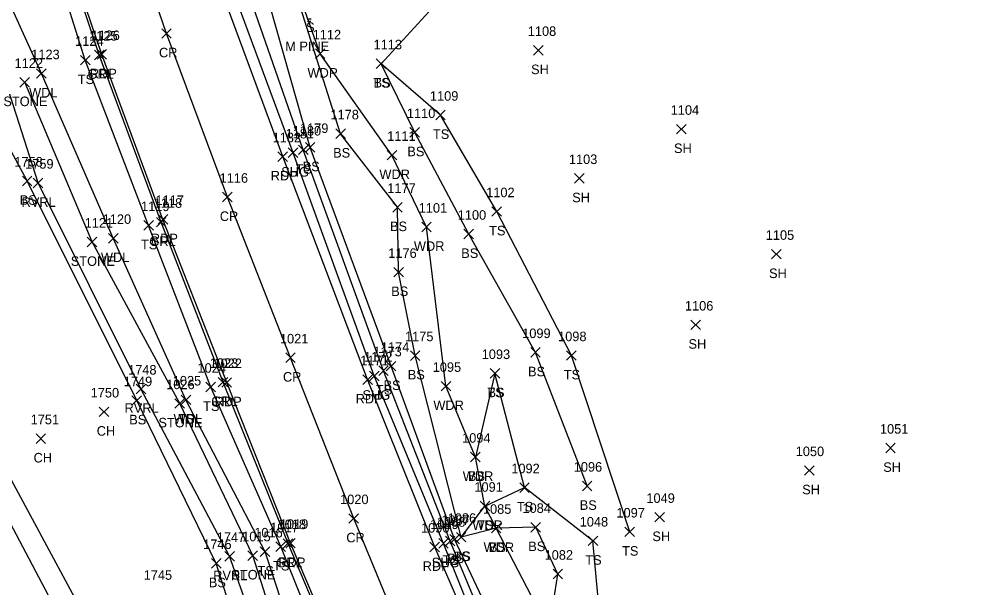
# Model space of a CAD drawing. Extents: x 1545627 to 1546562, y 571176 to 576667.
# Drawn here: x 1546172.5 to 1546373.5, y 571704.9 to 571824 of the extents above; entities that cross this region are included whole.
import ezdxf

# ---------------------------------------------------------------- set-up
doc = ezdxf.new("R2010")
doc.units = 0
for name, color, linetype in [('L_A', 7, 'Continuous'), ('L_C', 7, 'Continuous'), ('L_I', 7, 'Continuous'), ('L_TIC', 7, 'Continuous'), ('LASF', 7, 'Continuous'), ('LAWA', 7, 'Continuous'), ('LAWE', 7, 'Continuous'), ('LELB', 7, 'Continuous'), ('LTC', 7, 'Continuous'), ('P_A', 7, 'Continuous'), ('P_I', 7, 'Continuous'), ('P_TIC', 7, 'Continuous'), ('PET', 7, 'Continuous'), ('PRC', 7, 'Continuous'), ('PSU', 7, 'Continuous'), ('R_A', 7, 'Continuous'), ('R_I', 7, 'Continuous'), ('R_TIC', 7, 'Continuous'), ('RGR', 7, 'Continuous')]:
    doc.layers.add(name, color=color, linetype=linetype)

msp = doc.modelspace()

# ---------------------------------------------------------------- linework, layer by layer
at = {"layer": 'L_TIC'}
for points in [[(1546234.49, 571815.76), (1546236.49, 571817.76)], [(1546236.49, 571815.76), (1546234.49, 571817.76)], [(1546280.13, 571816.49), (1546282.13, 571818.49)], [(1546282.13, 571816.49), (1546280.13, 571818.49)], [(1546185.37, 571814.41), (1546187.37, 571816.41)], [(1546187.37, 571814.41), (1546185.37, 571816.41)], [(1546247.23, 571813.68), (1546249.23, 571815.68)], [(1546249.23, 571813.68), (1546247.23, 571815.68)], [(1546247.23, 571813.68), (1546249.23, 571815.68)], [(1546249.23, 571813.68), (1546247.23, 571815.68)], [(1546172.69, 571809.79), (1546174.69, 571811.79)], [(1546174.69, 571809.79), (1546172.69, 571811.79)], [(1546176.19, 571811.62), (1546178.19, 571813.62)], [(1546178.19, 571811.62), (1546176.19, 571813.62)], [(1546259.68, 571802.92), (1546261.68, 571804.92)], [(1546261.68, 571802.92), (1546259.68, 571804.92)], [(1546310.03, 571799.97), (1546312.03, 571801.97)], [(1546312.03, 571799.97), (1546310.03, 571801.97)], [(1546238.77, 571799.02), (1546240.77, 571801.02)], [(1546240.77, 571799.02), (1546238.77, 571801.02)], [(1546254.29, 571799.29), (1546256.29, 571801.29)], [(1546256.29, 571799.29), (1546254.29, 571801.29)], [(1546232.4, 571796.16), (1546234.4, 571798.16)], [(1546234.4, 571796.16), (1546232.4, 571798.16)], [(1546230.96, 571795.63), (1546232.96, 571797.63)], [(1546232.96, 571795.63), (1546230.96, 571797.63)], [(1546249.52, 571794.52), (1546251.52, 571796.52)], [(1546251.52, 571794.52), (1546249.52, 571796.52)], [(1546288.73, 571789.66), (1546290.73, 571791.66)], [(1546290.73, 571789.66), (1546288.73, 571791.66)], [(1546173.21, 571789.13), (1546175.21, 571791.13)], [(1546175.21, 571789.13), (1546173.21, 571791.13)], [(1546175.48, 571788.7), (1546177.48, 571790.7)], [(1546177.48, 571788.7), (1546175.48, 571790.7)], [(1546250.67, 571783.62), (1546252.67, 571785.62)], [(1546252.67, 571783.62), (1546250.67, 571785.62)], [(1546271.43, 571782.72), (1546273.43, 571784.72)], [(1546273.43, 571782.72), (1546271.43, 571784.72)], [(1546198.61, 571779.81), (1546200.61, 571781.81)], [(1546200.61, 571779.81), (1546198.61, 571781.81)], [(1546256.75, 571779.48), (1546258.75, 571781.48)], [(1546258.75, 571779.48), (1546256.75, 571781.48)], [(1546265.57, 571778), (1546267.57, 571780)], [(1546267.57, 571778), (1546265.57, 571780)], [(1546186.79, 571776.34), (1546188.79, 571778.34)], [(1546188.79, 571776.34), (1546186.79, 571778.34)], [(1546191.22, 571777.13), (1546193.22, 571779.13)], [(1546193.22, 571777.13), (1546191.22, 571779.13)], [(1546329.91, 571773.79), (1546331.91, 571775.79)], [(1546331.91, 571773.79), (1546329.91, 571775.79)], [(1546250.92, 571770.02), (1546252.92, 571772.02)], [(1546252.92, 571770.02), (1546250.92, 571772.02)], [(1546313.06, 571758.99), (1546315.06, 571760.99)], [(1546315.06, 571758.99), (1546313.06, 571760.99)], [(1546254.38, 571752.56), (1546256.38, 571754.56)], [(1546256.38, 571752.56), (1546254.38, 571754.56)], [(1546279.54, 571753.22), (1546281.54, 571755.22)], [(1546281.54, 571753.22), (1546279.54, 571755.22)], [(1546287.05, 571752.57), (1546289.05, 571754.57)], [(1546289.05, 571752.57), (1546287.05, 571754.57)], [(1546249.32, 571750.35), (1546251.32, 571752.35)], [(1546251.32, 571750.35), (1546249.32, 571752.35)], [(1546247.75, 571749.39), (1546249.75, 571751.39)], [(1546249.75, 571749.39), (1546247.75, 571751.39)], [(1546271.06, 571748.83), (1546273.06, 571750.83)], [(1546273.06, 571748.83), (1546271.06, 571750.83)], [(1546271.06, 571748.83), (1546273.06, 571750.83)], [(1546273.06, 571748.83), (1546271.06, 571750.83)], [(1546197.01, 571745.58), (1546199.01, 571747.58)], [(1546199.01, 571745.58), (1546197.01, 571747.58)], [(1546211.6, 571745.96), (1546213.6, 571747.96)], [(1546213.6, 571745.96), (1546211.6, 571747.96)], [(1546260.81, 571746.15), (1546262.81, 571748.15)], [(1546262.81, 571746.15), (1546260.81, 571748.15)], [(1546196.12, 571743.15), (1546198.12, 571745.15)], [(1546198.12, 571743.15), (1546196.12, 571745.15)], [(1546205.12, 571742.52), (1546207.12, 571744.52)], [(1546207.12, 571742.52), (1546205.12, 571744.52)], [(1546206.43, 571743.29), (1546208.43, 571745.29)], [(1546208.43, 571743.29), (1546206.43, 571745.29)], [(1546206.43, 571743.29), (1546208.43, 571745.29)], [(1546208.43, 571743.29), (1546206.43, 571745.29)], [(1546189.27, 571740.78), (1546191.27, 571742.78)], [(1546191.27, 571740.78), (1546189.27, 571742.78)], [(1546176.06, 571735.17), (1546178.06, 571737.17)], [(1546178.06, 571735.17), (1546176.06, 571737.17)], [(1546353.8, 571733.2), (1546355.8, 571735.2)], [(1546355.8, 571733.2), (1546353.8, 571735.2)], [(1546266.97, 571731.31), (1546268.97, 571733.31)], [(1546268.97, 571731.31), (1546266.97, 571733.31)], [(1546266.97, 571731.31), (1546268.97, 571733.31)], [(1546268.97, 571731.31), (1546266.97, 571733.31)], [(1546336.84, 571728.5), (1546338.84, 571730.5)], [(1546338.84, 571728.5), (1546336.84, 571730.5)], [(1546277.25, 571724.92), (1546279.25, 571726.92)], [(1546279.25, 571724.92), (1546277.25, 571726.92)], [(1546277.25, 571724.92), (1546279.25, 571726.92)], [(1546279.25, 571724.92), (1546277.25, 571726.92)], [(1546290.36, 571725.25), (1546292.36, 571727.25)], [(1546292.36, 571725.25), (1546290.36, 571727.25)], [(1546268.96, 571721.04), (1546270.96, 571723.04)], [(1546270.96, 571721.04), (1546268.96, 571723.04)], [(1546268.96, 571721.04), (1546270.96, 571723.04)], [(1546270.96, 571721.04), (1546268.96, 571723.04)], [(1546305.52, 571718.71), (1546307.52, 571720.71)], [(1546307.52, 571718.71), (1546305.52, 571720.71)], [(1546271.32, 571716.42), (1546273.32, 571718.42)], [(1546273.32, 571716.42), (1546271.32, 571718.42)], [(1546271.32, 571716.42), (1546273.32, 571718.42)], [(1546273.32, 571716.42), (1546271.32, 571718.42)], [(1546279.59, 571716.61), (1546281.59, 571718.61)], [(1546281.59, 571716.61), (1546279.59, 571718.61)], [(1546299.25, 571715.65), (1546301.25, 571717.65)], [(1546301.25, 571715.65), (1546299.25, 571717.65)], [(1546261.69, 571713.72), (1546263.69, 571715.72)], [(1546263.69, 571713.72), (1546261.69, 571715.72)], [(1546262.63, 571714.11), (1546264.63, 571716.11)], [(1546264.63, 571714.11), (1546262.63, 571716.11)], [(1546264, 571714.53), (1546266, 571716.53)], [(1546266, 571714.53), (1546264, 571716.53)], [(1546264, 571714.53), (1546266, 571716.53)], [(1546266, 571714.53), (1546264, 571716.53)], [(1546291.56, 571713.76), (1546293.56, 571715.76)], [(1546293.56, 571713.76), (1546291.56, 571715.76)], [(1546222.98, 571711.48), (1546224.98, 571713.48)], [(1546224.98, 571711.48), (1546222.98, 571713.48)], [(1546226.25, 571712.56), (1546228.25, 571714.56)], [(1546228.25, 571712.56), (1546226.25, 571714.56)], [(1546215.56, 571710.52), (1546217.56, 571712.52)], [(1546217.56, 571710.52), (1546215.56, 571712.52)], [(1546220.39, 571710.67), (1546222.39, 571712.67)], [(1546222.39, 571710.67), (1546220.39, 571712.67)], [(1546212.76, 571709.05), (1546214.76, 571711.05)], [(1546214.76, 571709.05), (1546212.76, 571711.05)], [(1546284.22, 571706.81), (1546286.22, 571708.81)], [(1546286.22, 571706.81), (1546284.22, 571708.81)]]:
    msp.add_lwpolyline(points, dxfattribs=at)
at = {"layer": 'LASF'}
msp.add_lwpolyline([(1546302.63, 571514.7), (1546284.96, 571554.64), (1546267.07, 571594.62), (1546248.5, 571636.16), (1546232.58, 571676.44), (1546221.39, 571711.67), (1546206.12, 571743.52), (1546187.79, 571777.34), (1546173.69, 571810.79)], dxfattribs=at)
at = {"layer": 'LAWA'}
for points in [[(1546207.43, 571744.29), (1546192.22, 571778.13), (1546177.19, 571812.62), (1546161.42, 571847.33), (1546150.88, 571886.7), (1546137.89, 571927.83), (1546130.49, 571965.71), (1546128.09, 572007.86), (1546121.49, 572030.97), (1546115.77, 572071.63), (1546116.87, 572083.76)], [(1546353.68, 571538.67), (1546333.05, 571577.3), (1546316.5, 571613.36), (1546304.35, 571639.71), (1546298.51, 571653.83), (1546282.89, 571690.9), (1546283.41, 571696.03), (1546272.32, 571717.42), (1546269.96, 571722.04), (1546267.97, 571732.31), (1546261.81, 571747.15), (1546257.75, 571780.48), (1546250.52, 571795.52), (1546235.49, 571816.76), (1546225.64, 571844.56)]]:
    msp.add_lwpolyline(points, dxfattribs=at)
at = {"layer": 'LAWE'}
for points in [[(1546291.68, 571509.09), (1546276, 571554.51), (1546265.8, 571586.47), (1546246.73, 571630.75), (1546234.82, 571659.95), (1546216.56, 571711.52), (1546198.01, 571746.58), (1546176.48, 571789.7), (1546167.29, 571818.28), (1546149.73, 571861.96), (1546132.38, 571905.18), (1546121.26, 571957.17), (1546118.8, 571996.68)], [(1546258.96, 571503.98), (1546247.25, 571543.2), (1546232.25, 571576.91), (1546212.48, 571618.99), (1546196.14, 571656.31), (1546182.65, 571695.75), (1546160.61, 571737.45), (1546138.23, 571773.59), (1546130.29, 571811.19), (1546113.32, 571843.26), (1546096.49, 571860.06), (1546088.58, 571875.57), (1546087.04, 571900.32), (1546085.16, 571952.92), (1546079.44, 571966.95), (1546077.79, 571985.49)]]:
    msp.add_lwpolyline(points, dxfattribs=at)
at = {"layer": 'LELB'}
for points in [[(1546347.4, 571535.24), (1546326.62, 571574.77), (1546309.35, 571609.13), (1546297.64, 571636.43), (1546292.79, 571646.22), (1546275.73, 571689.36), (1546263.63, 571715.11), (1546250.32, 571751.35), (1546233.4, 571797.16), (1546220.82, 571841.74), (1546218.61, 571853), (1546198.39, 571897.18), (1546185.1, 571947.88), (1546175.65, 571989.22), (1546174.94, 572003.26), (1546174.78, 572026.81), (1546167.55, 572047.44), (1546164.76, 572064.39), (1546160.42, 572092.89), (1546150.12, 572129.23)], [(1546346.37, 571534.64), (1546325.48, 571574.25), (1546308.89, 571608.63), (1546296.21, 571635.99), (1546273.97, 571687.64), (1546262.69, 571714.72), (1546248.75, 571750.39), (1546231.96, 571796.63), (1546217.3, 571838.7), (1546210.36, 571854.99), (1546196.65, 571897), (1546182.1, 571946.81), (1546169.64, 571995.56), (1546168.24, 572028.13), (1546158.04, 572044.97), (1546148.17, 572086.53), (1546140.64, 572120.6)], [(1546316.39, 571519.99), (1546295.99, 571560.57), (1546277.23, 571599.95), (1546257.92, 571640.86), (1546240.42, 571680.68), (1546227.25, 571713.56), (1546212.6, 571746.96), (1546199.61, 571780.81), (1546186.37, 571815.41), (1546174.93, 571851.82), (1546162.84, 571891.38), (1546151.94, 571927.81), (1546142.36, 571967.05), (1546132.26, 572008.4), (1546126.74, 572032.68), (1546118.89, 572071.99), (1546116.87, 572083.76)], [(1546289.09, 571508.47), (1546272.41, 571554.88), (1546264.55, 571586.76), (1546244.35, 571627.87), (1546230.42, 571657.81), (1546213.76, 571710.05), (1546197.12, 571744.15), (1546174.21, 571790.13), (1546160.91, 571814.7), (1546145.83, 571859.21), (1546131.62, 571904.03), (1546118.44, 571956.95), (1546115.97, 571995.99), (1546108.78, 572035.92), (1546103.73, 572068.58)], [(1546290.32, 571657.05), (1546276.57, 571693.2), (1546283.41, 571696.03), (1546285.22, 571707.81), (1546280.59, 571717.61), (1546272.32, 571717.42), (1546265, 571715.53), (1546255.38, 571753.56), (1546251.92, 571771.02), (1546251.67, 571784.62), (1546239.77, 571800.02), (1546225.64, 571844.56), (1546223.57, 571853.75), (1546206.91, 571899.08), (1546191.55, 571950.78), (1546183.98, 571991.38)], [(1546264.48, 571501.32), (1546248.81, 571543.43), (1546237.8, 571575.68), (1546217.63, 571618.65), (1546201.94, 571655.46), (1546187.64, 571696.37), (1546165.93, 571736.68), (1546143.43, 571776.5), (1546133.35, 571812.72), (1546115.39, 571843.89), (1546097.02, 571861.67), (1546090.93, 571875.32), (1546090.22, 571893.11)], [(1546291.36, 571726.25), (1546280.54, 571754.22), (1546266.57, 571779), (1546255.29, 571800.29), (1546248.23, 571814.68), (1546273.58, 571842.33), (1546296.06, 571877.38)], [(1546300.25, 571716.65), (1546288.05, 571753.57), (1546272.43, 571783.72), (1546260.68, 571803.92), (1546248.23, 571814.68)], [(1546265, 571715.53), (1546269.96, 571722.04), (1546278.25, 571725.92), (1546272.06, 571749.83)], [(1546272.06, 571749.83), (1546267.97, 571732.31)], [(1546235.21, 571678.3), (1546223.98, 571712.48), (1546207.43, 571744.29)], [(1546362.29, 571543.58), (1546342.98, 571580.07), (1546328.32, 571611.66), (1546309.49, 571653.11), (1546294.54, 571692.89), (1546292.56, 571714.76), (1546278.25, 571725.92)]]:
    msp.add_lwpolyline(points, dxfattribs=at)
at = {"layer": 'LTC'}
for p, q in [((1546233.62, 571823.98), (1546232.79, 571823.98)), ((1546233.54, 571823.48), (1546232.87, 571823.48))]:
    msp.add_line(p, q, dxfattribs=at)
at = {"layer": 'P_TIC'}
for points in [[(1546202.35, 571820.01), (1546204.35, 571822.01)], [(1546204.35, 571820.01), (1546202.35, 571822.01)], [(1546188.82, 571815.62), (1546190.82, 571817.62)], [(1546190.82, 571815.62), (1546188.82, 571817.62)], [(1546226.67, 571794.22), (1546228.67, 571796.22)], [(1546228.67, 571794.22), (1546226.67, 571796.22)], [(1546228.82, 571795.03), (1546230.82, 571797.03)], [(1546230.82, 571795.03), (1546228.82, 571797.03)], [(1546215.08, 571785.74), (1546217.08, 571787.74)], [(1546217.08, 571785.74), (1546215.08, 571787.74)], [(1546201.6, 571781.08), (1546203.6, 571783.08)], [(1546203.6, 571781.08), (1546201.6, 571783.08)], [(1546228.29, 571752.1), (1546230.29, 571754.1)], [(1546230.29, 571752.1), (1546228.29, 571754.1)], [(1546244.43, 571747.53), (1546246.43, 571749.53)], [(1546246.43, 571747.53), (1546244.43, 571749.53)], [(1546245.81, 571748.3), (1546247.81, 571750.3)], [(1546247.81, 571748.3), (1546245.81, 571750.3)], [(1546214.95, 571746.93), (1546216.95, 571748.93)], [(1546216.95, 571746.93), (1546214.95, 571748.93)], [(1546241.53, 571718.45), (1546243.53, 571720.45)], [(1546243.53, 571718.45), (1546241.53, 571720.45)], [(1546228.29, 571713.28), (1546230.29, 571715.28)], [(1546230.29, 571713.28), (1546228.29, 571715.28)], [(1546258.46, 571712.47), (1546260.46, 571714.47)], [(1546260.46, 571712.47), (1546258.46, 571714.47)], [(1546260.3, 571713.23), (1546262.3, 571715.23)], [(1546262.3, 571713.23), (1546260.3, 571715.23)]]:
    msp.add_lwpolyline(points, dxfattribs=at)
at = {"layer": 'PET'}
for points in [[(1546536.21, 571181.01), (1546508.17, 571223.67), (1546475.69, 571271.66), (1546448.41, 571311.32), (1546419.18, 571354.19), (1546394.92, 571390.86), (1546367.78, 571434.2), (1546346.92, 571469.65), (1546328.81, 571502.75), (1546318.67, 571520.99), (1546297.7, 571561.78), (1546279.07, 571601.48), (1546260.13, 571643.3), (1546242.96, 571682.18), (1546229.29, 571714.28), (1546215.95, 571747.93), (1546202.6, 571782.08), (1546189.82, 571816.62), (1546177.58, 571852.76), (1546165.76, 571891.53), (1546154.55, 571928.81), (1546144.5, 571967.92), (1546134.66, 572009.13)], [(1546559.08, 571194.5), (1546529.75, 571240.45), (1546499.79, 571284.88), (1546470.8, 571327.72), (1546443.13, 571367.68), (1546417.68, 571406.9), (1546392.95, 571446.31), (1546370.2, 571483.99), (1546352.76, 571515), (1546343.41, 571532.43), (1546322.94, 571573.04), (1546306.85, 571607.13), (1546293.98, 571634.56), (1546271.4, 571685.96), (1546259.46, 571713.47), (1546245.43, 571748.53), (1546227.67, 571795.22), (1546213.04, 571834.88), (1546205.18, 571857.76), (1546192.7, 571896.53), (1546178.72, 571945.47), (1546165.66, 571996.1)]]:
    msp.add_lwpolyline(points, dxfattribs=at)
at = {"layer": 'PRC'}
msp.add_lwpolyline([(1546547.34, 571187.72), (1546518.74, 571231.86), (1546487.31, 571278.43), (1546459.33, 571318.89), (1546430.57, 571360.77), (1546405.96, 571398.26), (1546380.25, 571440.1), (1546358.53, 571476.99), (1546340.41, 571508.44), (1546330.22, 571526.95), (1546310.11, 571567.47), (1546291.29, 571606.95), (1546272.42, 571649.01), (1546255.63, 571687.66), (1546242.53, 571719.45), (1546229.29, 571753.1), (1546216.08, 571786.74), (1546203.35, 571821.01), (1546191.26, 571856.19), (1546178.74, 571896.13), (1546167.5, 571932.69), (1546157.43, 571971.54), (1546147.89, 572011.79)], dxfattribs=at)
at = {"layer": 'PSU'}
msp.add_lwpolyline([(1546344.91, 571533.75), (1546324.24, 571573.75), (1546307.57, 571607.61), (1546295.25, 571635.34), (1546272.39, 571686.56), (1546261.3, 571714.23), (1546246.81, 571749.3), (1546229.82, 571796.03), (1546214.93, 571836.38), (1546208.22, 571856.11), (1546194.62, 571896.65), (1546180.08, 571945.81), (1546167.4, 571995.97), (1546161.66, 572024.84), (1546155.58, 572044.54)], dxfattribs=at)
at = {"layer": 'R_TIC'}
for points in [[(1546188.29, 571815.51), (1546190.29, 571817.51)], [(1546190.29, 571815.51), (1546188.29, 571817.51)], [(1546201.24, 571780.5), (1546203.24, 571782.5)], [(1546203.24, 571780.5), (1546201.24, 571782.5)], [(1546214.19, 571746.99), (1546216.19, 571748.99)], [(1546216.19, 571746.99), (1546214.19, 571748.99)], [(1546227.78, 571713.21), (1546229.78, 571715.21)], [(1546229.78, 571713.21), (1546227.78, 571715.21)]]:
    msp.add_lwpolyline(points, dxfattribs=at)
at = {"layer": 'RGR'}
msp.add_lwpolyline([(1546318.09, 571520.89), (1546297.39, 571561.7), (1546278.61, 571601.26), (1546259.67, 571643.05), (1546242.43, 571682.09), (1546228.78, 571714.21), (1546215.19, 571747.99), (1546202.24, 571781.5), (1546189.29, 571816.51), (1546177.18, 571852.71), (1546165.01, 571891.35), (1546154.15, 571928.78), (1546143.68, 571967.8), (1546133.91, 572008.79), (1546128.63, 572033), (1546121.13, 572073.3), (1546118.95, 572085.97)], dxfattribs=at)

# ---------------------------------------------------------------- texts
at = {"layer": 'L_A'}
for s, p in [('S', (1546232.55, 571821.32)), ('WDR', (1546232.85, 571811.76)), ('SH', (1546279.62, 571812.49)), ('TS', (1546184.78, 571810.41)), ('TS', (1546246.64, 571809.68)), ('BS', (1546246.67, 571809.68)), ('STONE', (1546169.23, 571805.79)), ('WDL', (1546174.61, 571807.62)), ('TS', (1546259.09, 571798.92)), ('SH', (1546309.52, 571795.97)), ('BS', (1546238.21, 571795.02)), ('BS', (1546253.73, 571795.29)), ('TS', (1546230.37, 571791.63)), ('BS', (1546231.84, 571792.16)), ('WDR', (1546247.89, 571790.52)), ('SH', (1546288.22, 571785.66)), ('BS', (1546172.65, 571785.13)), ('RVRL', (1546173.04, 571784.7)), ('BS', (1546250.11, 571779.62)), ('TS', (1546270.84, 571778.72)), ('TS', (1546198.02, 571775.81)), ('WDR', (1546255.11, 571775.48)), ('BS', (1546265.01, 571774)), ('STONE', (1546183.33, 571772.34)), ('WDL', (1546189.64, 571773.13)), ('SH', (1546329.4, 571769.79)), ('BS', (1546250.36, 571766.02)), ('SH', (1546312.55, 571754.99)), ('BS', (1546253.82, 571748.56)), ('BS', (1546278.98, 571749.22)), ('TS', (1546286.46, 571748.57)), ('TS', (1546247.16, 571745.39)), ('BS', (1546248.76, 571746.35)), ('TS', (1546270.47, 571744.83)), ('BS', (1546270.5, 571744.83)), ('RVRL', (1546194.58, 571741.58)), ('TS', (1546211.01, 571741.96)), ('WDR', (1546259.18, 571742.15)), ('BS', (1546195.56, 571739.15)), ('STONE', (1546201.66, 571738.52)), ('WDL', (1546204.85, 571739.29)), ('TS', (1546205.84, 571739.29)), ('CH', (1546188.76, 571736.78)), ('CH', (1546175.55, 571731.17)), ('BS', (1546266.41, 571727.31)), ('SH', (1546353.29, 571729.2)), ('WDR', (1546265.33, 571727.31)), ('SH', (1546336.33, 571724.5)), ('TS', (1546276.66, 571720.92)), ('TS', (1546276.66, 571720.92)), ('BS', (1546289.8, 571721.25)), ('WDR', (1546267.33, 571717.04)), ('TS', (1546268.37, 571717.04)), ('SH', (1546305, 571714.71)), ('WDR', (1546269.69, 571712.42)), ('BS', (1546270.77, 571712.42)), ('BS', (1546279.03, 571712.61)), ('TS', (1546298.66, 571711.65)), ('TS', (1546261.1, 571709.72)), ('BS', (1546262.07, 571710.11)), ('TS', (1546263.41, 571710.53)), ('BS', (1546263.44, 571710.53)), ('TS', (1546290.97, 571709.76)), ('TS', (1546222.39, 571707.48)), ('TS', (1546225.66, 571708.56)), ('RVRL', (1546213.13, 571706.52)), ('STONE', (1546216.93, 571706.67)), ('BS', (1546212.21, 571705.05))]:
    msp.add_text(s, height=2, dxfattribs=at).set_placement(p)
at = {"layer": 'L_C'}
msp.add_text('M PINE', height=2, dxfattribs=at).set_placement((1546228.19, 571817.32))
at = {"layer": 'L_I'}
for s, p in [('1112', (1546233.93, 571819.76)), ('1108', (1546278.93, 571820.49)), ('1124', (1546184.24, 571818.41)), ('1113', (1546246.67, 571817.68)), ('1113', (1546246.67, 571817.68)), ('1122', (1546171.57, 571813.79)), ('1123', (1546175.06, 571815.62)), ('1109', (1546258.46, 571806.92)), ('1104', (1546308.83, 571803.97)), ('1178', (1546237.65, 571803.02)), ('1110', (1546253.64, 571803.29)), ('1179', (1546231.27, 571800.16)), ('1180', (1546229.75, 571799.63)), ('1111', (1546249.53, 571798.52)), ('1103', (1546287.53, 571793.66)), ('1758', (1546171.52, 571793.13)), ('1759', (1546173.78, 571792.7)), ('1177', (1546249.54, 571787.62)), ('1102', (1546270.23, 571786.72)), ('1119', (1546198.04, 571783.81)), ('1101', (1546256.11, 571783.48)), ('1100', (1546264.28, 571782)), ('1121', (1546186.23, 571780.34)), ('1120', (1546190.01, 571781.13)), ('1105', (1546328.71, 571777.79)), ('1176', (1546249.74, 571774.02)), ('1106', (1546311.8, 571762.99)), ('1175', (1546253.25, 571756.56)), ('1099', (1546277.76, 571757.22)), ('1098', (1546285.27, 571756.57)), ('1174', (1546248.2, 571754.35)), ('1173', (1546246.62, 571753.39)), ('1093', (1546269.29, 571752.83)), ('1093', (1546269.29, 571752.83)), ('1748', (1546195.32, 571749.58)), ('1024', (1546209.83, 571749.96)), ('1095', (1546259.04, 571750.15)), ('1749', (1546194.41, 571747.15)), ('1026', (1546203.29, 571746.52)), ('1025', (1546204.66, 571747.29)), ('1025', (1546204.66, 571747.29)), ('1750', (1546187.49, 571744.78)), ('1751', (1546174.93, 571739.17)), ('1051', (1546352.6, 571737.2)), ('1094', (1546265.19, 571735.31)), ('1094', (1546265.19, 571735.31)), ('1050', (1546334.98, 571732.5)), ('1092', (1546275.48, 571728.92)), ('1092', (1546275.48, 571728.92)), ('1096', (1546288.54, 571729.25)), ('1091', (1546267.76, 571725.04)), ('1091', (1546267.76, 571725.04)), ('1049', (1546303.74, 571722.71)), ('1085', (1546269.55, 571720.42)), ('1085', (1546269.55, 571720.42)), ('1084', (1546277.82, 571720.61)), ('1097', (1546297.48, 571719.65)), ('1088', (1546259.92, 571717.72)), ('1087', (1546260.85, 571718.11)), ('1086', (1546262.18, 571718.53)), ('1086', (1546262.18, 571718.53)), ('1048', (1546289.79, 571717.76)), ('1016', (1546221.72, 571715.48)), ('1017', (1546225.05, 571716.56)), ('1747', (1546213.87, 571714.52)), ('1015', (1546219.19, 571714.67)), ('1746', (1546211.02, 571713.05)), ('1082', (1546282.45, 571710.81)), ('1745', (1546198.58, 571706.61))]:
    msp.add_text(s, height=2, dxfattribs=at).set_placement(p)
at = {"layer": 'P_A'}
for s, p in [('CR', (1546201.78, 571816.01)), ('RDP', (1546187.31, 571811.62)), ('RDP', (1546225.16, 571790.22)), ('SHG', (1546227.36, 571791.03)), ('CR', (1546214.51, 571781.74)), ('RDP', (1546200.09, 571777.08)), ('CR', (1546227.72, 571748.1)), ('RDP', (1546242.92, 571743.53)), ('SHG', (1546244.35, 571744.3)), ('RDP', (1546213.44, 571742.93)), ('CR', (1546240.96, 571714.45)), ('RDP', (1546226.77, 571709.28)), ('SHG', (1546258.84, 571709.23)), ('RDP', (1546256.95, 571708.47))]:
    msp.add_text(s, height=2, dxfattribs=at).set_placement(p)
at = {"layer": 'P_I'}
for s, p in [('1126', (1546187.64, 571819.62)), ('1182', (1546225.54, 571798.22)), ('1181', (1546228.27, 571799.03)), ('1116', (1546214.46, 571789.74)), ('1117', (1546201.04, 571785.08)), ('1021', (1546227.08, 571756.1)), ('1171', (1546243.87, 571751.53)), ('1172', (1546244.69, 571752.3)), ('1022', (1546213.18, 571750.93)), ('1020', (1546239.67, 571722.45)), ('1019', (1546227.07, 571717.28)), ('1090', (1546256.6, 571716.47)), ('1089', (1546258.52, 571717.23))]:
    msp.add_text(s, height=2, dxfattribs=at).set_placement(p)
at = {"layer": 'R_A'}
for p in [(1546186.84, 571811.51), (1546199.78, 571776.5), (1546212.73, 571742.99), (1546226.32, 571709.21)]:
    msp.add_text('GRL', height=2, dxfattribs=at).set_placement(p)
at = {"layer": 'R_I'}
for s, p in [('1125', (1546187.17, 571819.51)), ('1118', (1546200.68, 571784.5)), ('1023', (1546212.41, 571750.99)), ('1018', (1546226.58, 571717.21))]:
    msp.add_text(s, height=2, dxfattribs=at).set_placement(p)

doc.saveas('drawing.dxf')
